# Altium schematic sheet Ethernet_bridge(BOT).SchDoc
size 900 x 699 mm; SheetNumber: 1; SheetTotal: 1; SPICEModelCacheNLVBOJOE: <root> / <DocumentId>NLVBOJOE</DocumentId> / </root>
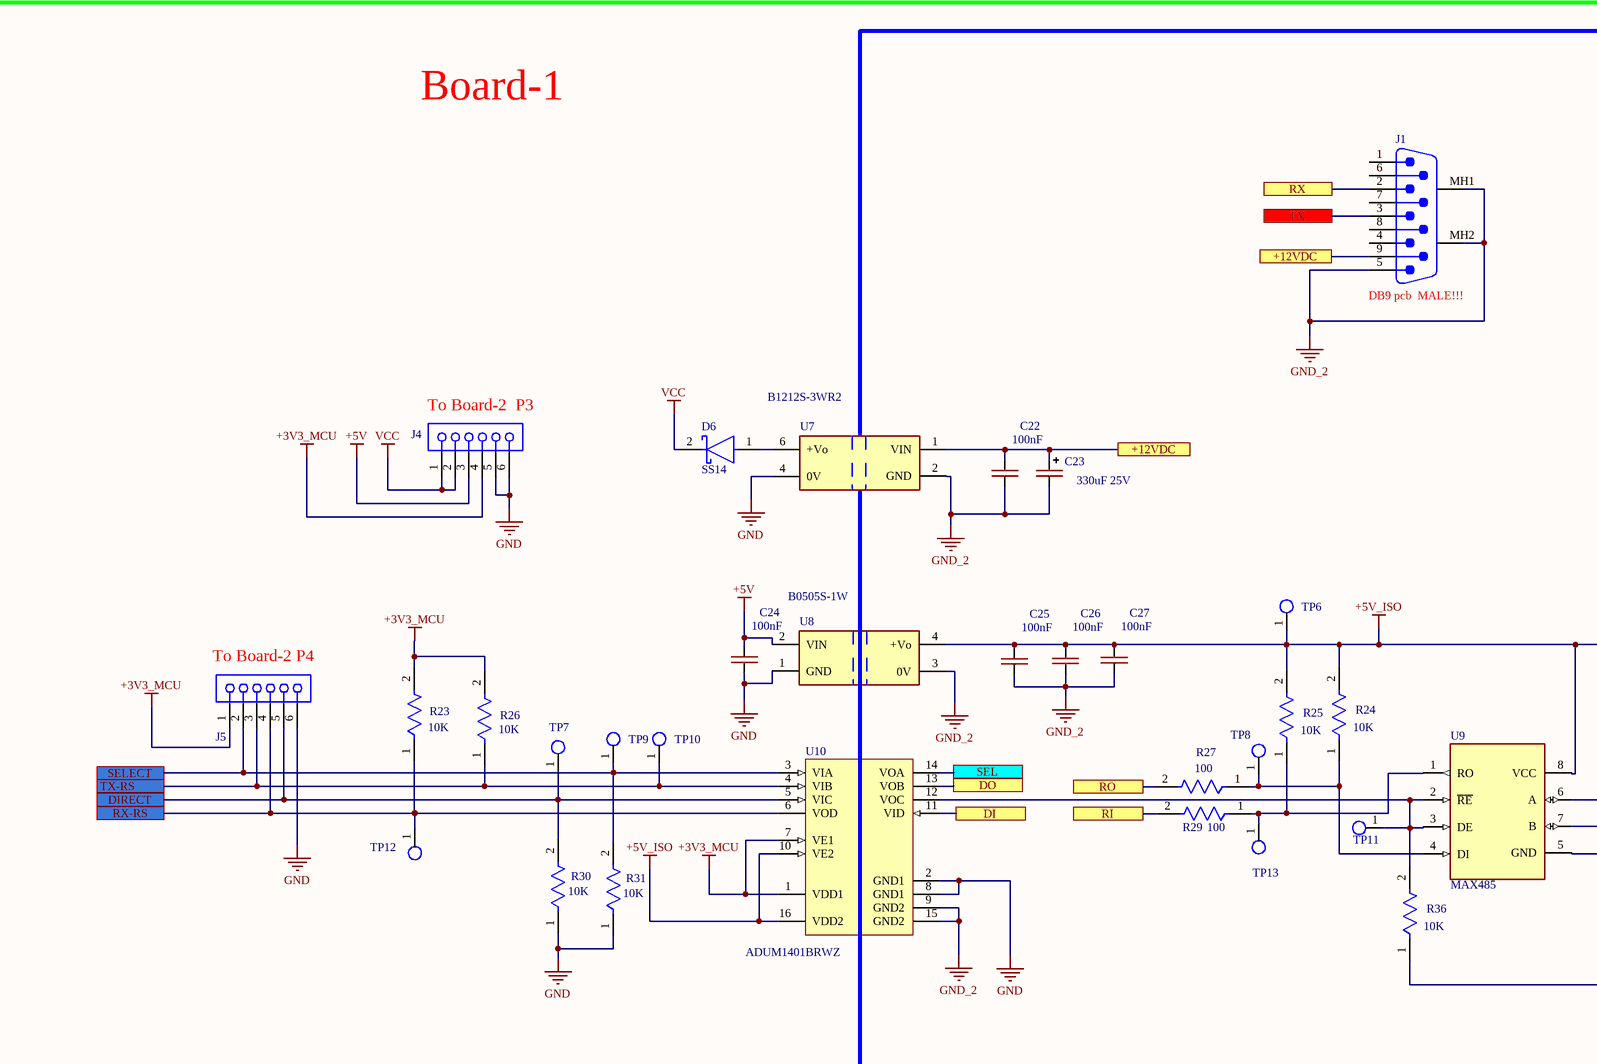
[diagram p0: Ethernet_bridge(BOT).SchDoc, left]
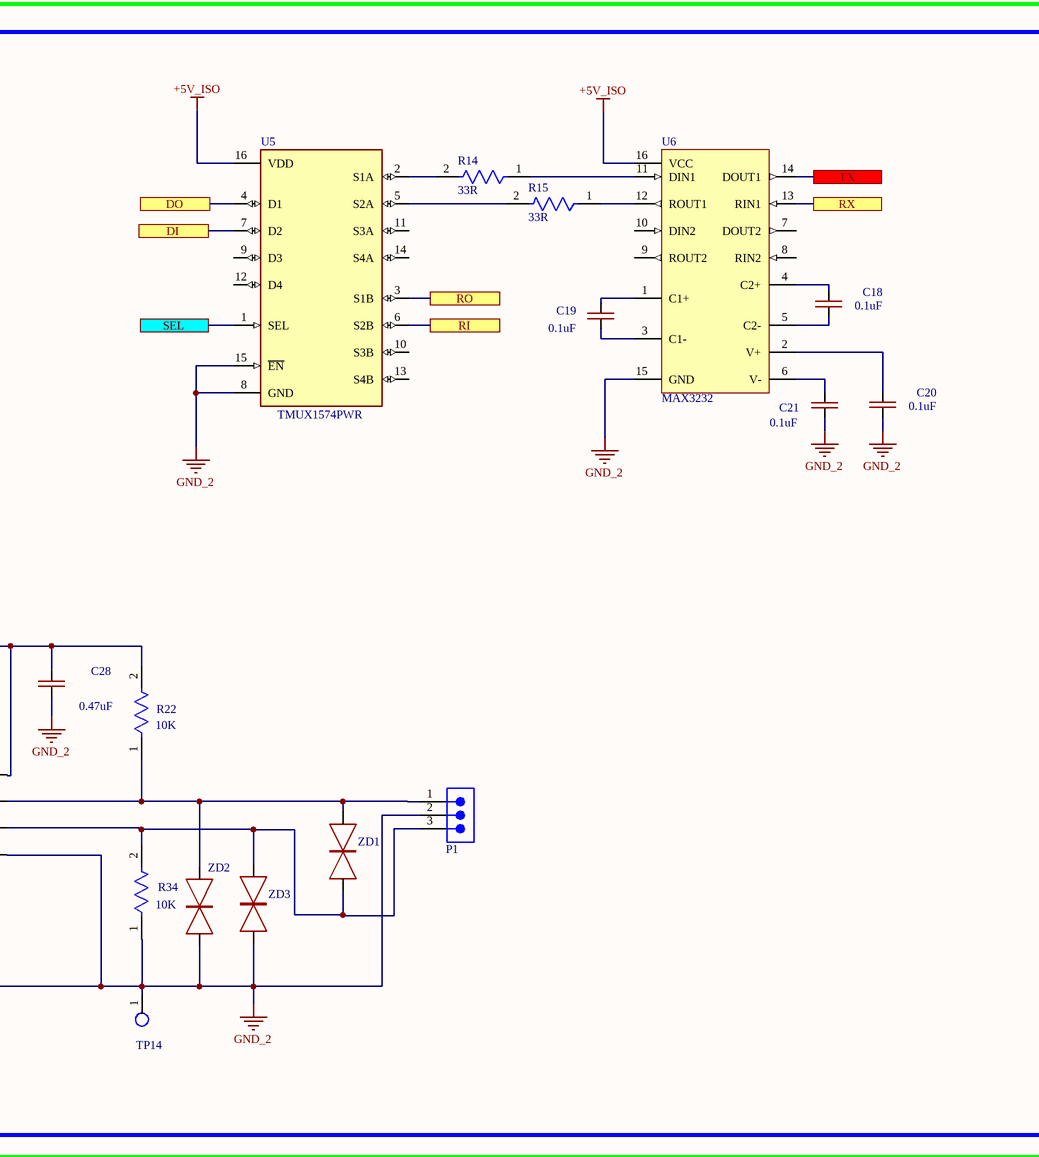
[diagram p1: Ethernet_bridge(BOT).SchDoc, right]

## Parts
C18  0.1uF  [CAP-0603]
C19  0.1uF  [CAP-0603]
C20  0.1uF  [CAP-0603]
C21  0.1uF  [CAP-0603]
C22  100nF  [CAP-0603]
C23  330uF 25V  [CAP_SMD_Size_E]
C24  100nF  [CAP-0603]
C25  100nF  [CAP-0603]
C26  100nF  [CAP-0603]
C27  100nF  [CAP-0603]
C28  0.47uF  [CAP-0805]
D6  SS14  [DO-214-AC]
J1  DB9 pcb  MALE!!!  [DB-9_2]
J4  61300611821  [61300611821]  (value not drawn)
J5  61300611821  [61300611821]  (value not drawn)
P1  691305340003  [691305340003]  (value not drawn)
R14  33R  [RES-0603]
R15  33R  [RES-0603]
R22  10K  [RES-0603]
R23  10K  [RES-0603]
R24  10K  [RES-0603]
R25  10K  [RES-0603]
R26  10K  [RES-0603]
R27  100  [RES-0603]
R29  100  [RES-0603]
R30  10K  [RES-0603]
R31  10K  [RES-0603]
R34  10K  [RES-0603]
R36  10K  [RES-0603]
TP6  Test_Point_PCB  [Test_Point]  (value not drawn)
TP7  Test_Point_PCB  [Test_Point]  (value not drawn)
TP8  Test_Point_PCB  [Test_Point]  (value not drawn)
TP9  Test_Point_PCB  [Test_Point]  (value not drawn)
TP10  Test_Point_PCB  [Test_Point]  (value not drawn)
TP11  Test_Point_PCB  [Test_Point]  (value not drawn)
TP12  Test_Point_PCB  [Test_Point]  (value not drawn)
TP13  (no value)  [Test_Point]
TP14  Test_Point_PCB  [Test_Point]  (value not drawn)
U5  TMUX1574PWR  [TSSOP-16-A]
U6  MAX3232  [SOIC-16-M]
U7  B1212S-3WR2  [B1212S-3WR2]
U8  B0505S-1W  [B0505S-1W]
U9  MAX485  [SOIC-8-MFG]
U10  ADUM1401BRWZ  [ADI-RW-16_M]
ZD1  P6SMB16CA  [DO-214AA]  (value not drawn)
ZD2  P6SMB16CA  [DO-214AA]  (value not drawn)
ZD3  P6SMB16CA  [DO-214AA]  (value not drawn)

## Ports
+12VDC (see Ethernet_bridge(BOT)[3B]), DI (see Ethernet_bridge(BOT)[3C]), DI (see Ethernet_bridge(BOT)[4B]), DIRECT, DO (see Ethernet_bridge(BOT)[3C]), DO (see Ethernet_bridge(BOT)[4B]), RI (see Ethernet_bridge(BOT)[3C]), RI (see Ethernet_bridge(BOT)[4B]), RO (see Ethernet_bridge(BOT)[3C]), RO (see Ethernet_bridge(BOT)[4B]), RX (see Ethernet_bridge(BOT)[3B]), RX (see Ethernet_bridge(BOT)[5B]), RX-RS, SEL (see Ethernet_bridge(BOT)[3C]), SEL (see Ethernet_bridge(BOT)[4B]), SELECT, TX (see Ethernet_bridge(BOT)[3B]), TX (see Ethernet_bridge(BOT)[5B]), TX-RS

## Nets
+3V3_MCU: J4.4 J5.1 R23.2 R26.2 U10.1(VDD1) U10.7(VE1)
+5V: C24.2 J4.3 U8.2(VIN)
+5V_ISO: C25.2 C26.2 C27.2 C28.1 R22.2 R24.2 R25.2 TP6.1(G9) U5.16(VDD) U6.16(VCC) U8.4(+Vo) U9.8(VCC) U10.10(VE2) U10.16(VDD2)
GND: C24.1 J4.5 J4.6 J5.6 R30.1 R31.1 U7.4(0V) U8.1(GND) U10.2(GND1) U10.8(GND1)
GND_2: C20.1 C21.1 C22.1 C23.2(-) C25.1 C26.1 C27.1 C28.2 J1.5 J1.MH1 J1.MH2 P1.2 R34.1 R36.1 TP14.1(G9) U5.8(GND) U5.15(~{EN}) U6.15(GND) U7.2(GND) U8.3(0V) U9.5(GND) U10.9(GND2) U10.15(GND2) ZD2.1(A) ZD3.1(A)
VCC: D6.2(C) J4.1 J4.2
+12VDC: C22.2 C23.1(+) J1.9 U7.1(VIN) ; port +12VDC
DI: U5.7(D2) U10.11(VID) ; port DI
DIRECT: J5.5 R30.2 TP7.1(G9) U10.5(VIC) ; port DIRECT
DO: U5.4(D1) U10.13(VOB) ; port DO
RI: R29.2 U5.6(S2B) ; port RI
RO: R27.2 U5.3(S1B) ; port RO
RX: J1.2 U6.13(RIN1) ; port RX
RX-RS: J5.4 R23.1 TP12.1(G9) U10.6(VOD) ; port RX-RS
SEL: U5.1(SEL) U10.14(VOA) ; port SEL
SELECT: J5.2 R31.2 TP9.1(G9) U10.3(VIA) ; port SELECT
TX: J1.3 U6.14(DOUT1) ; port TX
TX-RS: J5.3 R26.1 TP10.1(G9) U10.4(VIB) ; port TX-RS
NetC18_1: C18.1 U6.5(C2-)
NetC18_2: C18.2 U6.4(C2+)
NetC19_1: C19.1 U6.3(C1-)
NetC19_2: C19.2 U6.1(C1+)
NetC20_2: C20.2 U6.2(V+)
NetC21_2: C21.2 U6.6(V-)
NetD6_1: D6.1(A) U7.6(+Vo)
NetP1_1: P1.1 R22.1 U9.6(A) ZD1.2(A) ZD2.2(A)
NetP1_3: P1.3 R34.2 U9.7(B) ZD1.1(A) ZD3.2(A)
NetR14_1: R14.1 U6.11(DIN1)
NetR14_2: R14.2 U5.2(S1A)
NetR15_1: R15.1 U6.12(ROUT1)
NetR15_2: R15.2 U5.5(S2A)
NetR24_1: R24.1 R27.1 TP8.1(G9) U9.4(DI)
NetR25_1: R25.1 R29.1 TP13.1(G9) U9.1(RO)
NetR36_2: R36.2 TP11.1(G9) U9.2(~{RE}) U9.3(DE) U10.12(VOC)

Not connected (* = marked no-connect by the designer): J1 1 4 6 7 8; U5 9(D3) 10(S3B) 11(S3A) 12(D4) 13(S4B) 14(S4A); U6 7(DOUT2) 8(RIN2) 9(ROUT2) 10(DIN2)

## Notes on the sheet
- Board-1
- (near J4) To Board-2  P3
- (near J5) To Board-2 P4

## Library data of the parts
C18-C22 C24-C28 = CAP-NON-POLAR
C23 = CAP_POL_SMD
J1 = DB9
J4 J5 = 61300611821: WR-PHD Socket Header, THT, Vertical, pitch 2.54mm, 1 Row, 6P; Manufacturer: Wurth Elektronik; Contact Resistance: 20mΩ; Rated Current: 3A; Working Voltage: 250V; Withstanding Voltage: 500V
P1 = 691305340003: WR-TBL Series 3053 Horizontal PCB Header, THT, pitch 3.81mm, 3p; Manufacturer: Wurth Elektronik; Modularity: No; Rated Current: 12A; Working Voltage: 300V
R14 R15 R22-R27 R29-R31 R34 R36 = RES-CONST
TP6-TP14 = TP_PCB?: Test_Point
U10 = CMP-0534-00565-1: Quad Channel Digital Isolator, 2.5 KV rms Insulation Rating, 10 Mbps Data Rate, 50 ns Delay, Industrial, 16-pin SOIC (RW-16), Tube; Manufacturer: Analog Devices; Max Data Rate: 10Mbps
